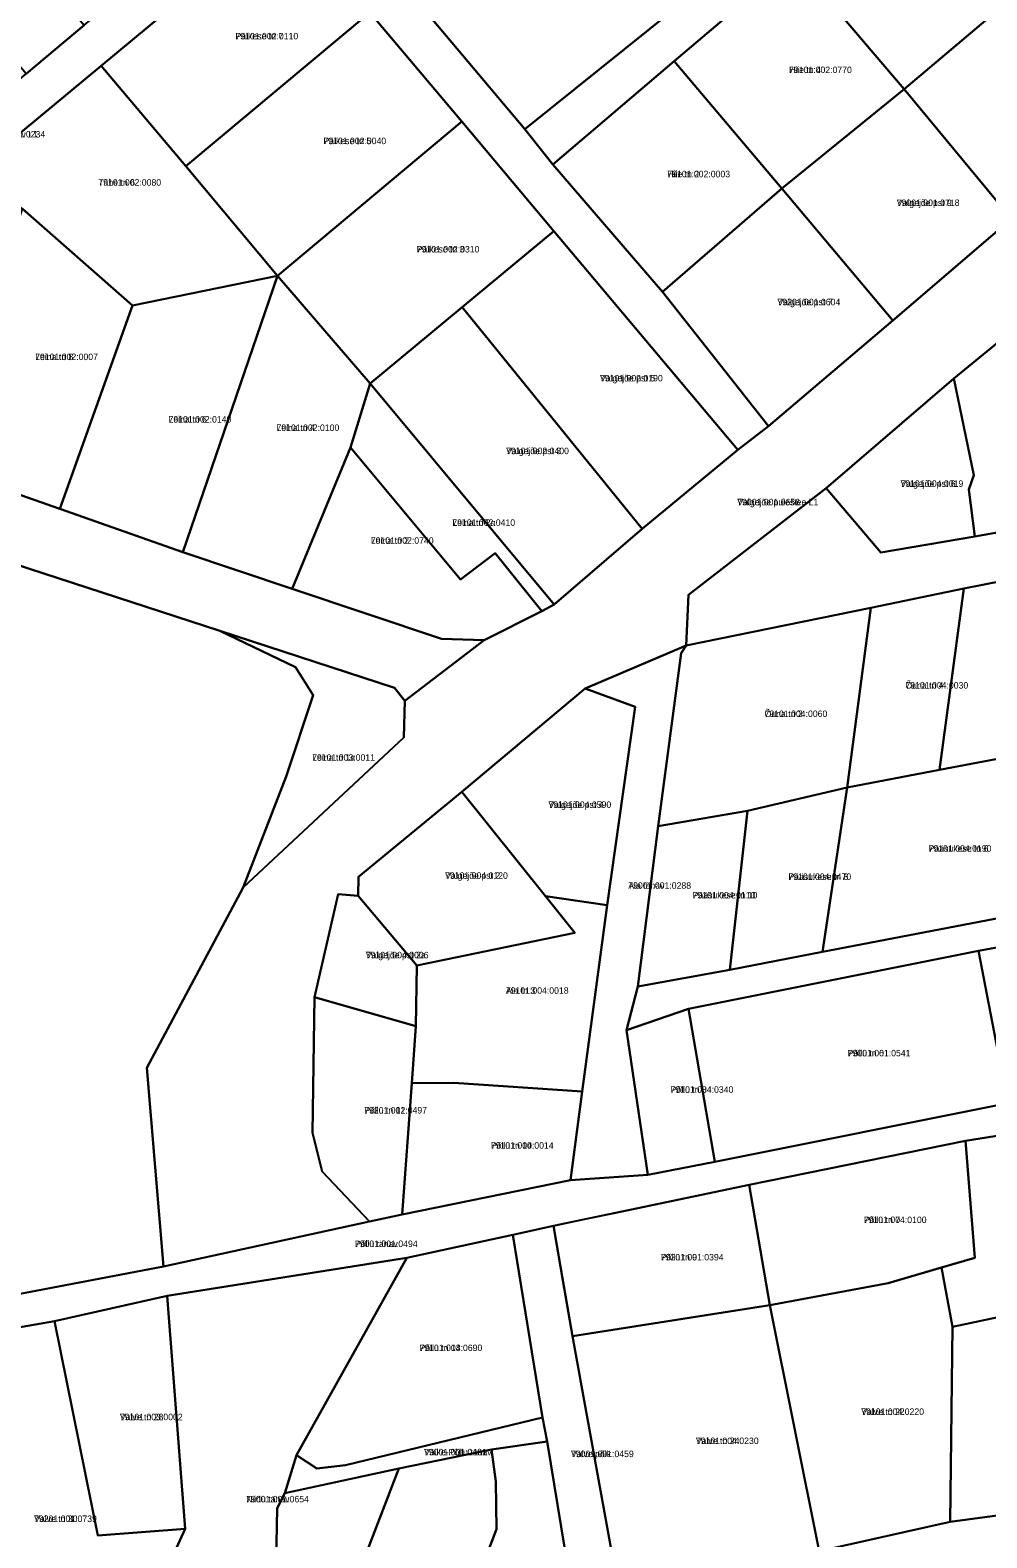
# Model space of a CAD drawing. Extents: x 587616 to 632239, y 6547421 to 6574977.
# Drawn here: x 611550.3 to 611771.3, y 6571383.6 to 6571731.9 of the extents above; entities that cross this region are included whole.
import ezdxf

# ---------------------------------------------------------------- set-up
doc = ezdxf.new("R2010")
doc.units = 0
for name, color, linetype in [('L_AADRESS', 7, 'Continuous'), ('PIIR', 7, 'Continuous'), ('TUNNUS', 7, 'Continuous')]:
    doc.layers.add(name, color=color, linetype=linetype)

msp = doc.modelspace()

# ---------------------------------------------------------------- linework, layer by layer
at = {"layer": 'PIIR'}
for points in [[(611713.77, 6571634.95), (611671.25, 6571685.43), (611650, 6571710.77), (611628.75, 6571735.95), (611609.2, 6571759), (611602.7, 6571766.58), (611579.32, 6571795.43), (611555.18, 6571823.56), (611563.05, 6571829.89), (611586.85, 6571801.61), (611610.82, 6571773.32), (611616.93, 6571765.84), (611640.68, 6571737.33), (611664.57, 6571708.99), (611670.97, 6571700.83), (611696.31, 6571671.43), (611720.8, 6571640.41)], [(611664.57, 6571708.99), (611699.25, 6571736.86), (611734.05, 6571767.26), (611769.24, 6571796.62), (611804.56, 6571826.12), (611810.91, 6571818.25), (611782.88, 6571794.92), (611755.22, 6571771.53), (611726.68, 6571748.18), (611699.01, 6571724.71), (611670.97, 6571700.83)], [(611835.77, 6571788.31), (611860.7, 6571758.31), (611776.98, 6571688.32), (611752.16, 6571718.25), (611779.77, 6571741.66), (611808.32, 6571765.1)], [(611726.68, 6571748.18), (611755.22, 6571771.53), (611779.77, 6571741.66), (611752.16, 6571718.25)], [(611482.43, 6571652.66), (611482.5, 6571647.61), (611467.85, 6571653.71), (611495.88, 6571677.1), (611522.47, 6571699.21), (611549.36, 6571721.82), (611562.77, 6571733), (611576.4, 6571744.42), (611602.7, 6571766.58), (611609.2, 6571759), (611566.71, 6571723.63), (611537.62, 6571699.64), (611509.76, 6571676.11), (611486.04, 6571655.92)], [(611640.68, 6571737.33), (611675.43, 6571766.39), (611699.25, 6571736.86), (611664.57, 6571708.99)], [(611539.08, 6571761.41), (611562.77, 6571733), (611549.36, 6571721.82), (611525.48, 6571749.97)], [(611566.71, 6571723.63), (611609.2, 6571759), (611628.75, 6571735.95), (611586.2, 6571700.5)], [(611699.01, 6571724.71), (611726.68, 6571748.18), (611752.16, 6571718.25), (611723.93, 6571695.34)], [(611586.2, 6571700.5), (611628.75, 6571735.95), (611650, 6571710.77), (611607.39, 6571675.16)], [(611566.71, 6571723.63), (611586.2, 6571700.5), (611607.39, 6571675.16), (611573.94, 6571668.3), (611548.52, 6571690.61), (611537.62, 6571699.64)], [(611699.01, 6571724.71), (611723.93, 6571695.34), (611696.31, 6571671.43), (611670.97, 6571700.83)], [(611749.51, 6571664.85), (611723.93, 6571695.34), (611752.16, 6571718.25), (611776.98, 6571688.32)], [(611607.39, 6571675.16), (611650, 6571710.77), (611671.25, 6571685.43), (611650.03, 6571667.89), (611628.8, 6571650.28)], [(611749.51, 6571664.85), (611720.8, 6571640.41), (611696.31, 6571671.43), (611723.93, 6571695.34)], [(611655.13, 6571591), (611636.79, 6571576.94), (611634.42, 6571579.97), (611594.05, 6571593.1), (611532.8, 6571613.07), (611461.84, 6571635.23), (611408.7, 6571653.51), (611402.66, 6571655.56), (611365.53, 6571668.22), (611335.83, 6571685.38), (611350.81, 6571692.38), (611391.61, 6571684.58), (611428.08, 6571668.12), (611467.85, 6571653.71), (611482.5, 6571647.61), (611528.92, 6571631.13), (611557.1, 6571621.3), (611585.56, 6571611.3), (611610.8, 6571602.83), (611645.3, 6571591.28)], [(611548.52, 6571690.61), (611573.94, 6571668.3), (611557.1, 6571621.3), (611528.92, 6571631.13), (611531.76, 6571639.56), (611536.65, 6571654.41)], [(611691.65, 6571616.69), (611650.03, 6571667.89), (611671.25, 6571685.43), (611713.77, 6571634.95)], [(611573.94, 6571668.3), (611607.39, 6571675.16), (611585.56, 6571611.3), (611557.1, 6571621.3)], [(611607.39, 6571675.16), (611628.8, 6571650.28), (611624.3, 6571635.45), (611610.8, 6571602.83), (611585.56, 6571611.3)], [(611650.03, 6571667.89), (611691.65, 6571616.69), (611671.29, 6571599.24), (611628.8, 6571650.28)], [(611767.08, 6571625.76), (611768.26, 6571629.12), (611763.67, 6571651.39), (611773.8, 6571659.74), (611780.22, 6571648.72), (611788.34, 6571639.8), (611790.41, 6571639.06), (611808.06, 6571645.86), (611815.48, 6571623.28), (611768.49, 6571614.89)], [(611628.8, 6571650.28), (611671.29, 6571599.24), (611668.45, 6571597.65), (611657.72, 6571611.07), (611649.69, 6571605.01), (611624.3, 6571635.45)], [(611763.67, 6571651.39), (611768.26, 6571629.12), (611767.08, 6571625.76), (611768.49, 6571614.89), (611746.81, 6571611.19), (611734.15, 6571626.12)], [(611624.3, 6571635.45), (611649.69, 6571605.01), (611657.72, 6571611.07), (611668.45, 6571597.65), (611655.13, 6571591), (611645.3, 6571591.28), (611610.8, 6571602.83)], [(611532.8, 6571613.07), (611594.05, 6571593.1), (611611.55, 6571584.74), (611615.68, 6571578.3), (611609.39, 6571559.45), (611599.5, 6571533.83), (611577.25, 6571492.16), (611581.04, 6571446.26), (611501.79, 6571431.16), (611461.56, 6571422.77), (611435.05, 6571411.17), (611427.47, 6571416.49), (611523.27, 6571570.76)], [(611765.92, 6571602.88), (611788.29, 6571607.33), (611782.24, 6571565.21), (611760.32, 6571560.98)], [(611744.43, 6571598.44), (611765.92, 6571602.88), (611760.32, 6571560.98), (611738.99, 6571556.91)], [(611695.33, 6571548), (611700.65, 6571587.95), (611701.77, 6571589.73), (611744.43, 6571598.44), (611738.99, 6571556.91), (611715.96, 6571551.51)], [(611594.05, 6571593.1), (611634.42, 6571579.97), (611636.79, 6571576.94), (611636.59, 6571568.46), (611599.5, 6571533.83), (611609.39, 6571559.45), (611615.68, 6571578.3), (611611.55, 6571584.74)], [(611675.11, 6571466.23), (611677.76, 6571486.73), (611683.56, 6571529.75), (611689.99, 6571575.55), (611678.47, 6571579.81), (611701.77, 6571589.73), (611700.65, 6571587.95), (611695.33, 6571548), (611690.65, 6571510.99), (611687.99, 6571500.86), (611692.92, 6571467.43)], [(611678.47, 6571579.81), (611689.99, 6571575.55), (611683.56, 6571529.75), (611669.31, 6571531.85), (611650.01, 6571555.9)], [(611738.99, 6571556.91), (611760.32, 6571560.98), (611782.24, 6571565.21), (611776.73, 6571527.29), (611733.29, 6571518.99)], [(611626.03, 6571531.92), (611626.14, 6571536.3), (611650.01, 6571555.9), (611669.31, 6571531.85), (611676.11, 6571523.33), (611639.62, 6571515.79)], [(611715.96, 6571551.51), (611738.99, 6571556.91), (611733.29, 6571518.99), (611711.87, 6571514.81)], [(611695.33, 6571548), (611715.96, 6571551.51), (611711.87, 6571514.81), (611690.65, 6571510.99)], [(611687.99, 6571500.86), (611690.65, 6571510.99), (611711.87, 6571514.81), (611733.29, 6571518.99), (611776.73, 6571527.29), (611782.06, 6571528.14), (611826.6, 6571536.74), (611869.21, 6571544.91), (611868.64, 6571536.17), (611857.87, 6571536.81), (611825.95, 6571530.21), (611816.44, 6571528.43), (611784.87, 6571522.04), (611769.32, 6571519.23), (611702.32, 6571505.79)], [(611639.34, 6571501.82), (611615.98, 6571508.53), (611621.39, 6571532.32), (611626.03, 6571531.92), (611639.62, 6571515.79)], [(611677.76, 6571486.73), (611648.15, 6571488.68), (611638.44, 6571488.6), (611639.34, 6571501.82), (611639.62, 6571515.79), (611676.11, 6571523.33), (611669.31, 6571531.85), (611683.56, 6571529.75)], [(611776.13, 6571483.99), (611769.32, 6571519.23), (611784.87, 6571522.04), (611789.07, 6571486.67)], [(611708.42, 6571470.43), (611702.32, 6571505.79), (611769.32, 6571519.23), (611776.13, 6571483.99)], [(611615.98, 6571508.53), (611639.34, 6571501.82), (611638.44, 6571488.6), (611636.22, 6571458.32), (611628.68, 6571456.69), (611617.71, 6571468.2), (611615.53, 6571477.18)], [(611687.99, 6571500.86), (611702.32, 6571505.79), (611708.42, 6571470.43), (611692.92, 6571467.43)], [(611638.44, 6571488.6), (611648.15, 6571488.68), (611677.76, 6571486.73), (611675.11, 6571466.23), (611636.22, 6571458.32)], [(611760.78, 6571446.05), (611768.46, 6571448.3), (611766.34, 6571475.32), (611839.32, 6571486.94), (611842.5, 6571467.56), (611859.35, 6571470.41), (611855.37, 6571454.35), (611819.09, 6571450.96), (611820.08, 6571444.33), (611763.36, 6571432.37)], [(611721.13, 6571437.33), (611716.33, 6571465.18), (611766.34, 6571475.32), (611768.46, 6571448.3), (611760.78, 6571446.05), (611748.45, 6571442.43)], [(611671.18, 6571455.7), (611678.67, 6571457.27), (611685.15, 6571458.63), (611716.33, 6571465.18), (611721.13, 6571437.33), (611675.56, 6571430.2), (611673.35, 6571443.05)], [(611661.77, 6571453.6), (611668.64, 6571411.42), (611623.09, 6571400.42), (611616.47, 6571399.6), (611611.79, 6571402.74), (611637.31, 6571448.31)], [(611688.63, 6571358.09), (611677.83, 6571356.13), (611669.69, 6571405.89), (611668.64, 6571411.42), (611661.77, 6571453.6), (611671.18, 6571455.66), (611675.56, 6571430.2), (611685.97, 6571372.91)], [(611637.31, 6571448.31), (611611.79, 6571402.74), (611609.07, 6571393.9), (611607.35, 6571390.46), (611606.79, 6571361.92), (611606.08, 6571342.06), (611583.66, 6571338.81), (611563, 6571335.15), (611586.1, 6571385.69), (611581.9, 6571439.5)], [(611721.13, 6571437.33), (611748.45, 6571442.43), (611760.78, 6571446.05), (611763.36, 6571432.37), (611762.8, 6571387.32), (611732.55, 6571380.56)], [(611763.36, 6571432.37), (611820.08, 6571444.33), (611822.73, 6571428.79), (611832.6, 6571430.3), (611838.87, 6571397.53), (611762.8, 6571387.32)], [(611581.9, 6571439.5), (611586.1, 6571385.69), (611565.92, 6571384.12), (611555.89, 6571433.64)], [(611675.56, 6571430.2), (611721.13, 6571437.33), (611732.55, 6571380.56), (611685.97, 6571372.91)], [(611563, 6571335.15), (611552.64, 6571333.21), (611546.75, 6571367.42), (611528.35, 6571368.37), (611518.46, 6571399.08), (611516.25, 6571426.74), (611555.89, 6571433.64), (611565.92, 6571384.12), (611586.1, 6571385.69)], [(611609.07, 6571393.9), (611611.79, 6571402.74), (611616.47, 6571399.6), (611623.09, 6571400.42), (611668.64, 6571411.42), (611669.69, 6571405.89), (611656.81, 6571404.05), (611635.47, 6571399.6)], [(611657.84, 6571396.6), (611656.81, 6571404.05), (611669.69, 6571405.89), (611677.83, 6571356.13), (611678.62, 6571351.69), (611643.09, 6571346.74), (611647.55, 6571358.25), (611658.03, 6571385.61)], [(611635.47, 6571399.6), (611656.81, 6571404.05), (611657.84, 6571396.6), (611658.03, 6571385.61), (611647.55, 6571358.25), (611617.6, 6571353.14)], [(611635.47, 6571399.6), (611617.6, 6571353.14), (611613.66, 6571343.16), (611606.08, 6571342.06), (611606.79, 6571361.92), (611607.35, 6571390.46), (611609.07, 6571393.9)], [(611859.19, 6571388.99), (611688.63, 6571358.09), (611685.97, 6571372.91), (611732.55, 6571380.56), (611762.8, 6571387.32), (611838.87, 6571397.53), (611858.19, 6571399.56)]]:
    msp.add_lwpolyline(points, close=True, dxfattribs=at)
for points in [[(611773.8, 6571659.74), (611763.67, 6571651.39), (611734.15, 6571626.12), (611702.36, 6571601.45), (611701.77, 6571589.73), (611678.47, 6571579.81), (611650.01, 6571555.9), (611626.14, 6571536.3), (611626.03, 6571531.92), (611621.39, 6571532.32), (611615.98, 6571508.53), (611615.53, 6571477.18), (611617.71, 6571468.2), (611628.68, 6571456.69), (611581.04, 6571446.26), (611577.25, 6571492.16), (611599.5, 6571533.83), (611636.59, 6571568.46), (611636.79, 6571576.94), (611655.13, 6571591), (611668.45, 6571597.65), (611671.29, 6571599.24), (611691.65, 6571616.69), (611713.77, 6571634.95), (611720.8, 6571640.41), (611749.51, 6571664.85), (611776.98, 6571688.32)], [(611788.29, 6571607.33), (611765.92, 6571602.88), (611744.43, 6571598.44), (611701.77, 6571589.73), (611702.36, 6571601.45), (611734.15, 6571626.12), (611746.81, 6571611.19), (611768.49, 6571614.89), (611815.48, 6571623.28)], [(611839.32, 6571486.94), (611766.34, 6571475.32), (611716.33, 6571465.18), (611671.18, 6571455.7), (611661.77, 6571453.6), (611637.31, 6571448.31), (611581.9, 6571439.5), (611555.89, 6571433.64), (611516.25, 6571426.74), (611470.81, 6571419.63), (611436.05, 6571404.12), (611435.05, 6571411.17), (611461.56, 6571422.77), (611501.79, 6571431.16), (611581.04, 6571446.26), (611628.68, 6571456.69), (611636.22, 6571458.32), (611675.11, 6571466.23), (611692.92, 6571467.43), (611708.42, 6571470.43), (611776.13, 6571483.99)]]:
    msp.add_lwpolyline(points, dxfattribs=at)

# ---------------------------------------------------------------- texts
at = {"layer": 'L_AADRESS'}
for s, p in [('Päikese tn 7', (611597.69, 6571729.75)), ('Hiie tn 4', (611725.58, 6571721.97)), ('Tähe tänav L1', (611539.25, 6571707.09)), ('Päikese tn 5', (611618.01, 6571705.55)), ('Tähe tn 6', (611566.02, 6571695.96)), ('Hiie tn 2', (611697.45, 6571697.9)), ('Valgejõe pst 9', (611750.45, 6571691.26)), ('Päikese tn 3', (611639.56, 6571680.53)), ('Valgejõe pst 7', (611722.91, 6571668.33)), ('Leina tn 8', (611551.43, 6571655.67)), ('Valgejõe pst 5', (611681.9, 6571650.74)), ('Leina tn 6', (611582.25, 6571641.23)), ('Leina tn 4', (611607.18, 6571639.3)), ('Valgejõe pst 3', (611660.22, 6571633.94)), ('Valgejõe pst 6', (611751.32, 6571626.39)), ('Valgejõe puiestee L1', (611713.61, 6571622.12)), ('Leina tn 2a', (611647.79, 6571617.37)), ('Leina tn 2', (611628.97, 6571613.23)), ('Õuna tn 4', (611752.46, 6571579.79)), ('Õuna tn 2', (611719.91, 6571573.22)), ('Leina tn 1a', (611615.42, 6571563.11)), ('Valgejõe pst 4', (611670, 6571552.22)), ('Pääsukese tn 6', (611757.82, 6571542.1)), ('Valgejõe pst 2', (611646.12, 6571535.84)), ('Pääsukese tn 8', (611725.43, 6571535.59)), ('Aia tänav', (611688.44, 6571533.54)), ('Pääsukese tn 10', (611703.3, 6571531.31)), ('Valgejõe pst 2a', (611627.8, 6571517.48)), ('Aia tn 3', (611660.15, 6571509.29)), ('Põllu tn 6', (611739.12, 6571494.83)), ('Põllu tn 8', (611698.21, 6571486.41)), ('Põllu tn 12', (611627.44, 6571481.62)), ('Põllu tn 10', (611656.69, 6571473.5)), ('Põllu tn 7', (611742.84, 6571456.32)), ('Põllu tänav', (611625.28, 6571450.79)), ('Põllu tn 9', (611695.95, 6571447.69)), ('Põllu tn 13', (611640.21, 6571426.75)), ('Valve tn 28', (611571, 6571410.78)), ('Valve tn 22', (611742.25, 6571412)), ('Valve tn 24', (611704.05, 6571405.27)), ('Väike-Põllu tänav', (611641.25, 6571402.66)), ('Valve põik', (611675.2, 6571402.25)), ('Niidu tänav', (611600.16, 6571391.8)), ('Valve tn 30', (611551.18, 6571387.27))]:
    msp.add_text(s, height=1.5, dxfattribs=at).set_placement(p)
at = {"layer": 'TUNNUS'}
for s, p in [('79101:002:0110', (611597.69, 6571729.75)), ('79101:002:0770', (611725.58, 6571721.97)), ('79001:001:0234', (611539.25, 6571707.09)), ('79101:002:0040', (611618.01, 6571705.55)), ('79101:002:0080', (611566.02, 6571695.96)), ('79101:002:0003', (611697.45, 6571697.9)), ('79001:001:0718', (611750.45, 6571691.26)), ('79101:002:0310', (611639.56, 6571680.53)), ('79201:001:0604', (611722.91, 6571668.33)), ('79101:002:0007', (611551.43, 6571655.67)), ('79101:002:0190', (611681.9, 6571650.74)), ('79101:002:0140', (611582.25, 6571641.23)), ('79101:002:0100', (611607.18, 6571639.3)), ('79101:002:0400', (611660.22, 6571633.94)), ('79101:004:0019', (611751.32, 6571626.39)), ('79001:001:0656', (611713.61, 6571622.12)), ('79101:002:0410', (611647.79, 6571617.37)), ('79101:002:0740', (611628.97, 6571613.23)), ('79101:004:0030', (611752.46, 6571579.79)), ('79101:004:0060', (611719.91, 6571573.22)), ('79101:003:0011', (611615.42, 6571563.11)), ('79101:004:0590', (611670, 6571552.22)), ('79101:004:0190', (611757.82, 6571542.1)), ('79101:004:0120', (611646.12, 6571535.84)), ('79001:001:0288', (611688.44, 6571533.54)), ('79101:004:0470', (611725.43, 6571535.59)), ('79101:004:0110', (611703.3, 6571531.31)), ('79101:004:0006', (611627.8, 6571517.48)), ('79101:004:0018', (611660.15, 6571509.29)), ('79001:001:0541', (611739.12, 6571494.83)), ('79101:004:0340', (611698.21, 6571486.41)), ('79201:001:0497', (611627.44, 6571481.62)), ('79101:004:0014', (611656.69, 6571473.5)), ('79101:004:0100', (611742.84, 6571456.32)), ('79001:001:0494', (611625.28, 6571450.79)), ('79201:001:0394', (611695.95, 6571447.69)), ('79101:004:0690', (611640.21, 6571426.75)), ('79101:003:0002', (611571, 6571410.78)), ('79101:004:0220', (611742.25, 6571412)), ('79101:004:0230', (611704.05, 6571405.27)), ('79001:001:0481', (611641.25, 6571402.66)), ('79001:001:0459', (611675.2, 6571402.25)), ('79001:001:0654', (611600.16, 6571391.8)), ('79201:001:0739', (611551.18, 6571387.27))]:
    msp.add_text(s, height=1.5, dxfattribs=at).set_placement(p)

doc.saveas('drawing.dxf')
